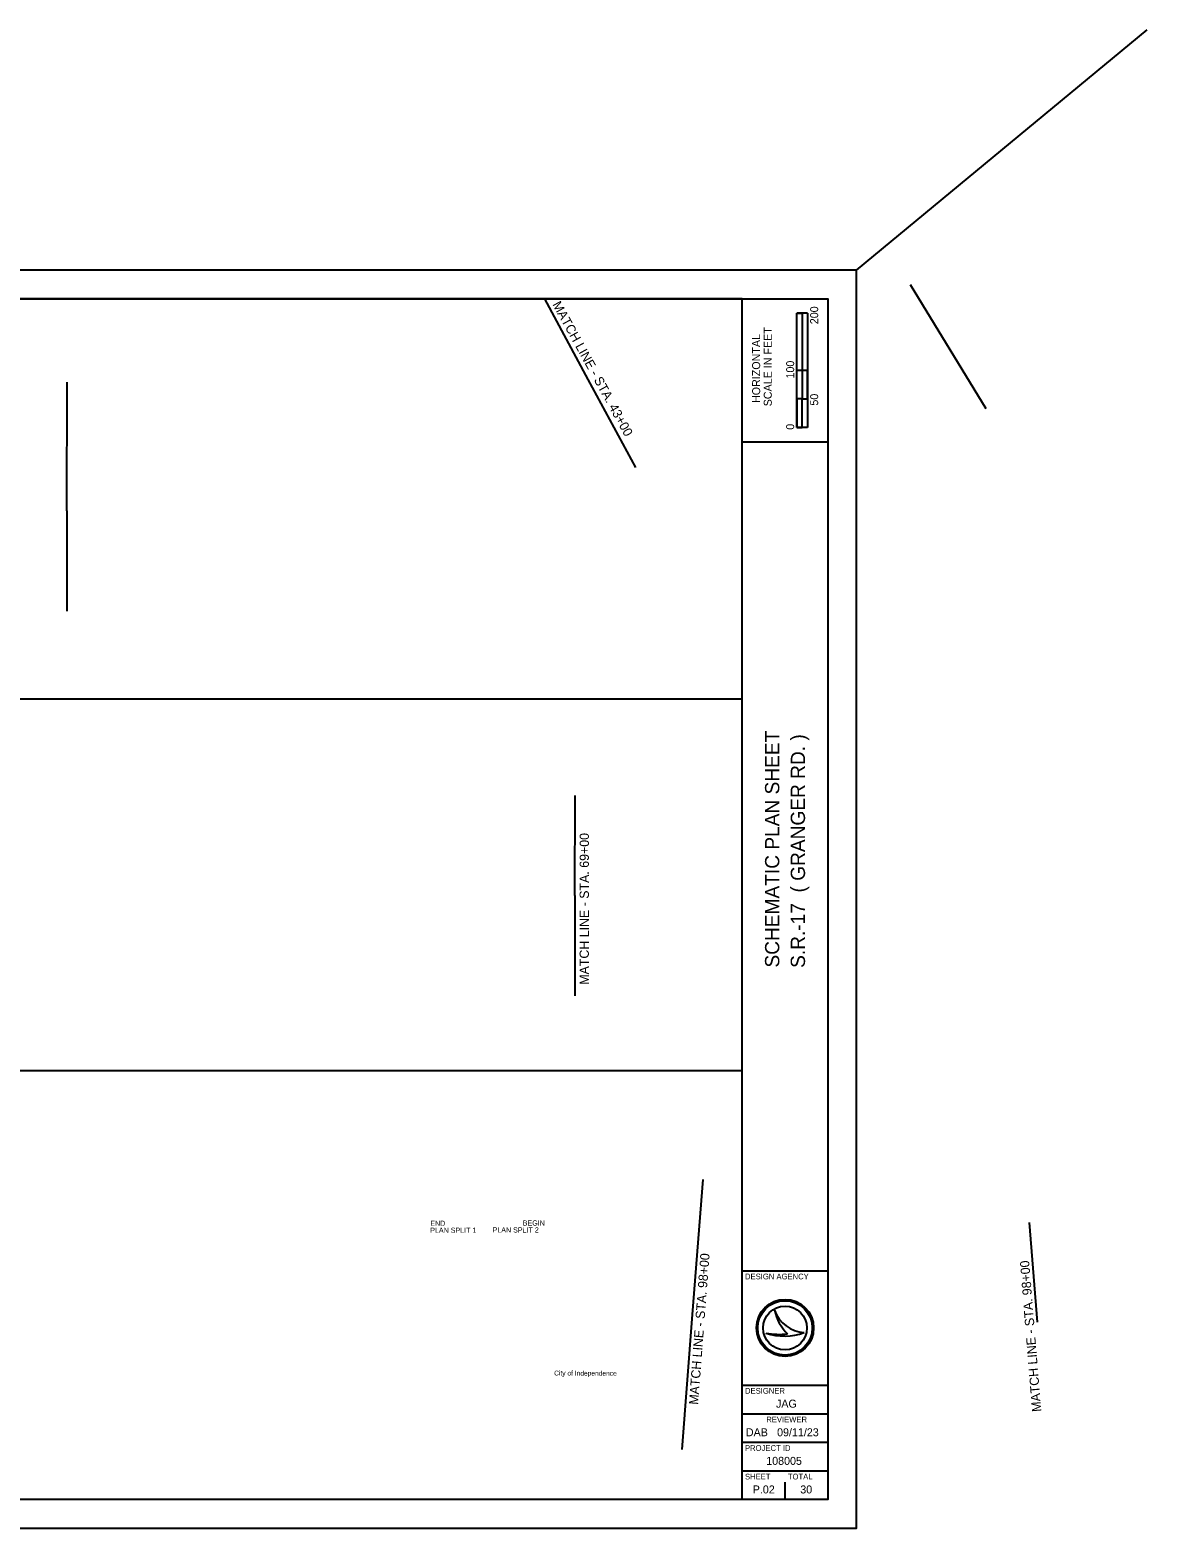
# Model space of a CAD drawing. Extents: x -3578 to 3908, y -278 to 2620.
# Drawn here: x 1954 to 3908, y 0 to 2620 of the extents above; entities that cross this region are included whole.
import ezdxf

# ---------------------------------------------------------------- set-up
doc = ezdxf.new("R2010")
doc.units = 0
for name, color, linetype in [('Level 1', 7, 'Continuous'), ('Level 2', 7, 'Continuous'), ('Level 3', 7, 'Continuous'), ('Level 4', 7, 'Continuous')]:
    doc.layers.add(name, color=color, linetype=linetype)

msp = doc.modelspace()

# ---------------------------------------------------------------- linework, layer by layer
at = {"layer": 'Level 1'}
msp.add_lwpolyline([(0, 0), (3400, 0), (3400, 2200), (0, 2200)], close=True, dxfattribs=at)
at = {"layer": 'Level 2'}
for p, q in [((3200, 2150), (150, 2150)), ((3200, 50), (3200, 2150)), ((3200, 1900), (3350, 1900)), ((3200, 1450), (150, 1450)), ((3200, 800), (150, 800)), ((3200, 450), (3350, 450)), ((3200, 250), (3350, 250)), ((3200, 200), (3350, 200)), ((3200, 150), (3350, 150)), ((3200, 100), (3350, 100))]:
    msp.add_line(p, q, dxfattribs=at)
msp.add_lwpolyline([(150, 2150), (3350, 2150), (3350, 50), (150, 50)], close=True, dxfattribs=at)
at = {"layer": 'Level 3'}
for p, q in [((2854.1, 2150), (2930.3, 2008.9)), ((3295.7, 1925), (3295.7, 2125)), ((3314.4, 2125), (3295.7, 2125)), ((3295.7, 2025), (3295.7, 2125)), ((3295.7, 2125), (3305, 2125)), ((3305, 2125), (3305.1, 2125)), ((3305.1, 2125), (3305.1, 2025)), ((3314.4, 2125), (3314.4, 1925)), ((3305.1, 2025), (3295.7, 2025)), ((3314.3, 2025), (3305, 2025)), ((3305, 2025), (3305, 1975)), ((3314.3, 1975), (3314.3, 2025)), ((2018.8, 1779.4), (2019.3, 2004.5)), ((2930.3, 2008.9), (3013.5, 1854.9)), ((3305, 1975), (3295.7, 1975)), ((3295.7, 1975), (3295.7, 1925)), ((3305, 1925), (3305, 1975)), ((3305, 1975), (3314.3, 1975)), ((3314.4, 1925), (3295.7, 1925)), ((3295.7, 1925), (3305, 1925)), ((2018.8, 1779.4), (2018.4, 1603.9)), ((2907.4, 1106.2), (2907.6, 1281.2)), ((2907.4, 1106.2), (2907.1, 931.2)), ((3113.4, 373.6), (3131.9, 609.9)), ((3702.2, 534.4), (3716, 360)), ((3095, 137.2), (3113.4, 373.6)), ((3256.7, 381), (3256.7, 381)), ((3241.7, 341), (3241.7, 341)), ((3275, 350), (3275, 350)), ((3308.7, 341.9), (3308.7, 341.9)), ((3275, 50), (3275, 80)), ((3237.5, 67.5), (3237.5, 67.5))]:
    msp.add_line(p, q, dxfattribs=at)
for radius in [50, 47.7, 47.7, 38.2]:
    msp.add_circle((3275, 350), radius, dxfattribs=at)
for centre, radius, start, end in [((3311.6, 399.8), 58, 198.9257, 198.9319), ((3334.7, 397), 79.6, 191.6379, 191.6421), ((3311.6, 399.8), 58, 198.9319, 267.1657), ((3334.7, 397), 79.6, 191.6421, 226.0947), ((3273.9, 437), 101.3, 251.4576, 290.0832), ((3264.8, 465.4), 126.6, 259.4964, 259.4995), ((3273.9, 437), 101.3, 251.4527, 251.4576), ((3264.8, 465.4), 126.6, 259.4995, 276.6672)]:
    msp.add_arc(centre, radius, start, end, dxfattribs=at)
at = {"layer": 'Level 4'}
for p, q in [((3400, 2200), (3908.3, 2620.4)), ((3494, 2175.3), (3626, 1958.1))]:
    msp.add_line(p, q, dxfattribs=at)

# ---------------------------------------------------------------- texts
at = {"layer": 'Level 3'}
for s, height, rotation, p in [('MATCH LINE - STA. 43+00', 16.2, 298.8197, (2867.5, 2140.3)), ('200', 14, 90, (3333, 2105.7)), ('SCALE IN FEET', 14, 90, (3251.8, 1962.1)), ('HORIZONTAL', 14, 90, (3231.5, 1967.9)), ('100', 14, 90, (3291, 2010.7)), ('50', 14, 90, (3333, 1963.3)), ('0', 14, 90, (3291, 1921.1)), ('SCHEMATIC PLAN SHEET', 25, 90, (3265, 980.4)), ('S.R.-17  ( GRANGER RD. )', 25, 90, (3310, 979.8)), ('MATCH LINE - STA. 69+00', 16.2, 89.968, (2931.8, 950.3)), ('END', 9, 359.9073, (2654.4, 528.7)), ('PLAN SPLIT 1', 9, 359.9073, (2654.3, 516.5)), ('PLAN SPLIT 2', 9, 359.9073, (2763.4, 517)), ('BEGIN', 9, 359.9073, (2816.1, 529.1)), ('MATCH LINE - STA. 98+00', 16.2, 85.6032, (3122.9, 215.3)), ('MATCH LINE - STA. 98+00', 16.2, 94.6316, (3723.4, 203.9)), ('City of Independence', 8.4, 359.7637, (2871.1, 266.9))]:
    msp.add_text(s, height=height, rotation=rotation, dxfattribs=at).set_placement(p)
for s, height, p in [('DESIGN AGENCY', 10, (3205, 435)), ('DESIGNER', 10, (3205, 235)), ('JAG', 14, (3259.2, 210.5)), ('REVIEWER', 10, (3242.2, 185)), ('DAB', 14, (3206.5, 160.5)), ('09/11/23', 14, (3261.1, 160.5)), ('PROJECT ID', 10, (3205, 135)), ('108005', 14, (3242.1, 110.5)), ('SHEET', 10, (3205, 85)), ('TOTAL', 10, (3280, 85)), ('P.02', 14, (3218.5, 60.5)), ('30', 14, (3301.7, 60.5))]:
    msp.add_text(s, height=height, dxfattribs=at).set_placement(p)

doc.saveas('drawing.dxf')
